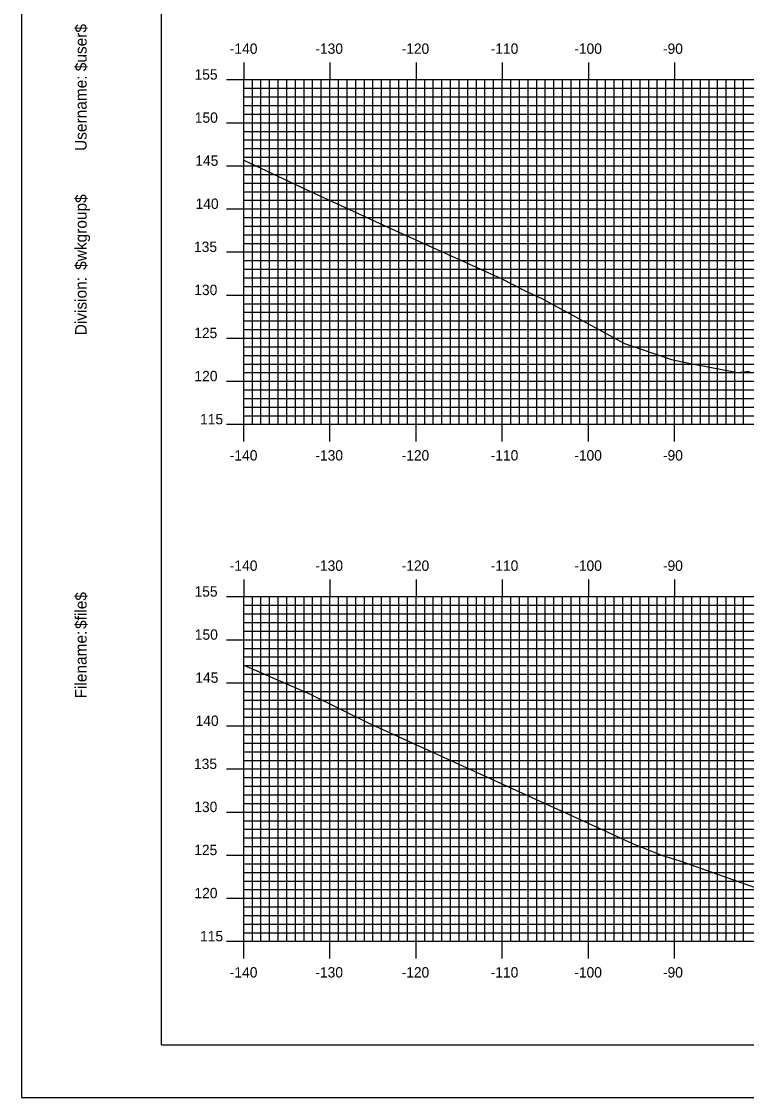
# Model space of a CAD drawing. Extents: x 852320 to 852663, y 366605 to 366825.
# Drawn here: x 852319.7 to 852403.8, y 366604.9 to 366729.8 of the extents above; entities that cross this region are included whole.
import ezdxf

# ---------------------------------------------------------------- set-up
doc = ezdxf.new("R2010")
doc.units = 0
for name, color, linetype in [('BORDER', 7, 'Continuous'), ('H_V ANNOTATION', 7, 'Continuous'), ('MAJOR', 7, 'Continuous'), ('MINOR', 7, 'Continuous'), ('PLOT BOUNDARY', 7, 'Continuous'), ('S_Roadway_Centerline', 7, 'Continuous')]:
    doc.layers.add(name, color=color, linetype=linetype)

msp = doc.modelspace()

# ---------------------------------------------------------------- linework, layer by layer
at = {"layer": 'BORDER'}
msp.add_lwpolyline([(852335.88, 366611.06), (852655.88, 366611.06), (852655.88, 366821.06), (852335.88, 366821.06)], close=True, dxfattribs=at)
at = {"layer": 'MAJOR'}
for p, q in [((852345.48, 366725.06), (852345.48, 366723.06)), ((852355.48, 366725.06), (852355.48, 366723.06)), ((852365.48, 366725.06), (852365.48, 366723.06)), ((852375.48, 366725.06), (852375.48, 366723.06)), ((852385.48, 366725.06), (852385.48, 366723.06)), ((852395.48, 366725.06), (852395.48, 366723.06)), ((852343.47, 366723.06), (852345.48, 366723.06)), ((852345.48, 366723.06), (852625.48, 366723.06)), ((852345.48, 366683.06), (852345.48, 366723.06)), ((852345.48, 366683.06), (852345.48, 366723.06)), ((852345.48, 366723.06), (852625.48, 366723.06)), ((852355.48, 366683.06), (852355.48, 366723.06)), ((852365.48, 366683.06), (852365.48, 366723.06)), ((852375.48, 366683.06), (852375.48, 366723.06)), ((852385.48, 366683.06), (852385.48, 366723.06)), ((852395.48, 366683.06), (852395.48, 366723.06)), ((852343.47, 366718.06), (852345.48, 366718.06)), ((852345.48, 366718.06), (852625.48, 366718.06)), ((852343.47, 366713.06), (852345.48, 366713.06)), ((852345.48, 366713.06), (852625.48, 366713.06)), ((852343.47, 366708.06), (852345.48, 366708.06)), ((852345.48, 366708.06), (852625.48, 366708.06)), ((852343.47, 366703.06), (852345.48, 366703.06)), ((852345.48, 366703.06), (852625.48, 366703.06)), ((852343.47, 366698.06), (852345.48, 366698.06)), ((852345.48, 366698.06), (852625.48, 366698.06)), ((852343.47, 366693.06), (852345.48, 366693.06)), ((852345.48, 366693.06), (852625.48, 366693.06)), ((852343.47, 366688.06), (852345.48, 366688.06)), ((852345.48, 366688.06), (852625.48, 366688.06)), ((852343.47, 366683.06), (852345.48, 366683.06)), ((852345.48, 366683.06), (852625.48, 366683.06)), ((852345.48, 366683.06), (852625.48, 366683.06)), ((852345.48, 366681.05), (852345.48, 366683.06)), ((852355.48, 366681.05), (852355.48, 366683.06)), ((852365.48, 366681.05), (852365.48, 366683.06)), ((852375.48, 366681.05), (852375.48, 366683.06)), ((852385.48, 366681.05), (852385.48, 366683.06)), ((852395.48, 366681.05), (852395.48, 366683.06)), ((852345.48, 366665.06), (852345.48, 366663.06)), ((852355.48, 366665.06), (852355.48, 366663.06)), ((852365.48, 366665.06), (852365.48, 366663.06)), ((852375.48, 366665.06), (852375.48, 366663.06)), ((852385.48, 366665.06), (852385.48, 366663.06)), ((852395.48, 366665.06), (852395.48, 366663.06)), ((852343.47, 366663.06), (852345.48, 366663.06)), ((852345.48, 366663.06), (852625.48, 366663.06)), ((852345.48, 366623.06), (852345.48, 366663.06)), ((852345.48, 366623.06), (852345.48, 366663.06)), ((852345.48, 366663.06), (852625.48, 366663.06)), ((852355.48, 366623.06), (852355.48, 366663.06)), ((852365.48, 366623.06), (852365.48, 366663.06)), ((852375.48, 366623.06), (852375.48, 366663.06)), ((852385.48, 366623.06), (852385.48, 366663.06)), ((852395.48, 366623.06), (852395.48, 366663.06)), ((852343.47, 366658.06), (852345.48, 366658.06)), ((852345.48, 366658.06), (852625.48, 366658.06)), ((852343.47, 366653.06), (852345.48, 366653.06)), ((852345.48, 366653.06), (852625.48, 366653.06)), ((852343.47, 366648.06), (852345.48, 366648.06)), ((852345.48, 366648.06), (852625.48, 366648.06)), ((852343.47, 366643.06), (852345.48, 366643.06)), ((852345.48, 366643.06), (852625.48, 366643.06)), ((852343.47, 366638.06), (852345.48, 366638.06)), ((852345.48, 366638.06), (852625.48, 366638.06)), ((852343.47, 366633.06), (852345.48, 366633.06)), ((852345.48, 366633.06), (852625.48, 366633.06)), ((852343.47, 366628.06), (852345.48, 366628.06)), ((852345.48, 366628.06), (852625.48, 366628.06)), ((852343.47, 366623.06), (852345.48, 366623.06)), ((852345.48, 366623.06), (852625.48, 366623.06)), ((852345.48, 366623.06), (852625.48, 366623.06)), ((852345.48, 366621.05), (852345.48, 366623.06)), ((852355.48, 366621.05), (852355.48, 366623.06)), ((852365.48, 366621.05), (852365.48, 366623.06)), ((852375.48, 366621.05), (852375.48, 366623.06)), ((852385.48, 366621.05), (852385.48, 366623.06)), ((852395.48, 366621.05), (852395.48, 366623.06))]:
    msp.add_line(p, q, dxfattribs=at)
at = {"layer": 'MINOR'}
for p, q in [((852346.48, 366683.06), (852346.48, 366723.06)), ((852347.48, 366683.06), (852347.48, 366723.06)), ((852348.48, 366683.06), (852348.48, 366723.06)), ((852349.48, 366683.06), (852349.48, 366723.06)), ((852350.48, 366683.06), (852350.48, 366723.06)), ((852351.48, 366683.06), (852351.48, 366723.06)), ((852352.48, 366683.06), (852352.48, 366723.06)), ((852353.48, 366683.06), (852353.48, 366723.06)), ((852354.48, 366683.06), (852354.48, 366723.06)), ((852356.48, 366683.06), (852356.48, 366723.06)), ((852357.48, 366683.06), (852357.48, 366723.06)), ((852358.48, 366683.06), (852358.48, 366723.06)), ((852359.48, 366683.06), (852359.48, 366723.06)), ((852360.48, 366683.06), (852360.48, 366723.06)), ((852361.48, 366683.06), (852361.48, 366723.06)), ((852362.48, 366683.06), (852362.48, 366723.06)), ((852363.48, 366683.06), (852363.48, 366723.06)), ((852364.48, 366683.06), (852364.48, 366723.06)), ((852366.48, 366683.06), (852366.48, 366723.06)), ((852367.48, 366683.06), (852367.48, 366723.06)), ((852368.48, 366683.06), (852368.48, 366723.06)), ((852369.48, 366683.06), (852369.48, 366723.06)), ((852370.48, 366683.06), (852370.48, 366723.06)), ((852371.48, 366683.06), (852371.48, 366723.06)), ((852372.48, 366683.06), (852372.48, 366723.06)), ((852373.48, 366683.06), (852373.48, 366723.06)), ((852374.48, 366683.06), (852374.48, 366723.06)), ((852376.48, 366683.06), (852376.48, 366723.06)), ((852377.48, 366683.06), (852377.48, 366723.06)), ((852378.48, 366683.06), (852378.48, 366723.06)), ((852379.48, 366683.06), (852379.48, 366723.06)), ((852380.48, 366683.06), (852380.48, 366723.06)), ((852381.48, 366683.06), (852381.48, 366723.06)), ((852382.48, 366683.06), (852382.48, 366723.06)), ((852383.48, 366683.06), (852383.48, 366723.06)), ((852384.48, 366683.06), (852384.48, 366723.06)), ((852386.48, 366683.06), (852386.48, 366723.06)), ((852387.48, 366683.06), (852387.48, 366723.06)), ((852388.48, 366683.06), (852388.48, 366723.06)), ((852389.48, 366683.06), (852389.48, 366723.06)), ((852390.48, 366683.06), (852390.48, 366723.06)), ((852391.48, 366683.06), (852391.48, 366723.06)), ((852392.48, 366683.06), (852392.48, 366723.06)), ((852393.48, 366683.06), (852393.48, 366723.06)), ((852394.48, 366683.06), (852394.48, 366723.06)), ((852396.48, 366683.06), (852396.48, 366723.06)), ((852397.48, 366683.06), (852397.48, 366723.06)), ((852398.48, 366683.06), (852398.48, 366723.06)), ((852399.48, 366683.06), (852399.48, 366723.06)), ((852400.48, 366683.06), (852400.48, 366723.06)), ((852401.48, 366683.06), (852401.48, 366723.06)), ((852402.48, 366683.06), (852402.48, 366723.06)), ((852403.48, 366683.06), (852403.48, 366723.06)), ((852345.48, 366722.06), (852625.48, 366722.06)), ((852345.48, 366722.06), (852347.48, 366722.06)), ((852345.48, 366721.06), (852625.48, 366721.06)), ((852345.48, 366721.06), (852347.48, 366721.06)), ((852345.48, 366720.06), (852625.48, 366720.06)), ((852345.48, 366720.06), (852347.48, 366720.06)), ((852345.48, 366719.06), (852625.48, 366719.06)), ((852345.48, 366719.06), (852347.48, 366719.06)), ((852345.48, 366717.06), (852625.48, 366717.06)), ((852345.48, 366717.06), (852347.48, 366717.06)), ((852345.48, 366716.06), (852625.48, 366716.06)), ((852345.48, 366716.06), (852347.48, 366716.06)), ((852345.48, 366715.06), (852625.48, 366715.06)), ((852345.48, 366715.06), (852347.48, 366715.06)), ((852345.48, 366714.06), (852625.48, 366714.06)), ((852345.48, 366714.06), (852347.48, 366714.06)), ((852345.48, 366712.06), (852625.48, 366712.06)), ((852345.48, 366712.06), (852347.48, 366712.06)), ((852345.48, 366711.06), (852625.48, 366711.06)), ((852345.48, 366711.06), (852347.48, 366711.06)), ((852345.48, 366710.06), (852625.48, 366710.06)), ((852345.48, 366710.06), (852347.48, 366710.06)), ((852345.48, 366709.06), (852625.48, 366709.06)), ((852345.48, 366709.06), (852347.48, 366709.06)), ((852345.48, 366707.06), (852625.48, 366707.06)), ((852345.48, 366707.06), (852347.48, 366707.06)), ((852345.48, 366706.06), (852625.48, 366706.06)), ((852345.48, 366706.06), (852347.48, 366706.06)), ((852345.48, 366705.06), (852625.48, 366705.06)), ((852345.48, 366705.06), (852347.48, 366705.06)), ((852345.48, 366704.06), (852625.48, 366704.06)), ((852345.48, 366704.06), (852347.48, 366704.06)), ((852345.48, 366702.06), (852625.48, 366702.06)), ((852345.48, 366702.06), (852347.48, 366702.06)), ((852345.48, 366701.06), (852625.48, 366701.06)), ((852345.48, 366701.06), (852347.48, 366701.06)), ((852345.48, 366700.06), (852625.48, 366700.06)), ((852345.48, 366700.06), (852347.48, 366700.06)), ((852345.48, 366699.06), (852625.48, 366699.06)), ((852345.48, 366699.06), (852347.48, 366699.06)), ((852345.48, 366697.06), (852625.48, 366697.06)), ((852345.48, 366697.06), (852347.48, 366697.06)), ((852345.48, 366696.06), (852625.48, 366696.06)), ((852345.48, 366696.06), (852347.48, 366696.06)), ((852345.48, 366695.06), (852625.48, 366695.06)), ((852345.48, 366695.06), (852347.48, 366695.06)), ((852345.48, 366694.06), (852625.48, 366694.06)), ((852345.48, 366694.06), (852347.48, 366694.06)), ((852345.48, 366692.06), (852625.48, 366692.06)), ((852345.48, 366692.06), (852347.48, 366692.06)), ((852345.48, 366691.06), (852625.48, 366691.06)), ((852345.48, 366691.06), (852347.48, 366691.06)), ((852345.48, 366690.06), (852625.48, 366690.06)), ((852345.48, 366690.06), (852347.48, 366690.06)), ((852345.48, 366689.06), (852625.48, 366689.06)), ((852345.48, 366689.06), (852347.48, 366689.06)), ((852345.48, 366687.06), (852625.48, 366687.06)), ((852345.48, 366687.06), (852347.48, 366687.06)), ((852345.48, 366686.06), (852625.48, 366686.06)), ((852345.48, 366686.06), (852347.48, 366686.06)), ((852345.48, 366685.06), (852625.48, 366685.06)), ((852345.48, 366685.06), (852347.48, 366685.06)), ((852345.48, 366684.06), (852625.48, 366684.06)), ((852345.48, 366684.06), (852347.48, 366684.06)), ((852346.48, 366623.06), (852346.48, 366663.06)), ((852347.48, 366623.06), (852347.48, 366663.06)), ((852348.48, 366623.06), (852348.48, 366663.06)), ((852349.48, 366623.06), (852349.48, 366663.06)), ((852350.48, 366623.06), (852350.48, 366663.06)), ((852351.48, 366623.06), (852351.48, 366663.06)), ((852352.48, 366623.06), (852352.48, 366663.06)), ((852353.48, 366623.06), (852353.48, 366663.06)), ((852354.48, 366623.06), (852354.48, 366663.06)), ((852356.48, 366623.06), (852356.48, 366663.06)), ((852357.48, 366623.06), (852357.48, 366663.06)), ((852358.48, 366623.06), (852358.48, 366663.06)), ((852359.48, 366623.06), (852359.48, 366663.06)), ((852360.48, 366623.06), (852360.48, 366663.06)), ((852361.48, 366623.06), (852361.48, 366663.06)), ((852362.48, 366623.06), (852362.48, 366663.06)), ((852363.48, 366623.06), (852363.48, 366663.06)), ((852364.48, 366623.06), (852364.48, 366663.06)), ((852366.48, 366623.06), (852366.48, 366663.06)), ((852367.48, 366623.06), (852367.48, 366663.06)), ((852368.48, 366623.06), (852368.48, 366663.06)), ((852369.48, 366623.06), (852369.48, 366663.06)), ((852370.48, 366623.06), (852370.48, 366663.06)), ((852371.48, 366623.06), (852371.48, 366663.06)), ((852372.48, 366623.06), (852372.48, 366663.06)), ((852373.48, 366623.06), (852373.48, 366663.06)), ((852374.48, 366623.06), (852374.48, 366663.06)), ((852376.48, 366623.06), (852376.48, 366663.06)), ((852377.48, 366623.06), (852377.48, 366663.06)), ((852378.48, 366623.06), (852378.48, 366663.06)), ((852379.48, 366623.06), (852379.48, 366663.06)), ((852380.48, 366623.06), (852380.48, 366663.06)), ((852381.48, 366623.06), (852381.48, 366663.06)), ((852382.48, 366623.06), (852382.48, 366663.06)), ((852383.48, 366623.06), (852383.48, 366663.06)), ((852384.48, 366623.06), (852384.48, 366663.06)), ((852386.48, 366623.06), (852386.48, 366663.06)), ((852387.48, 366623.06), (852387.48, 366663.06)), ((852388.48, 366623.06), (852388.48, 366663.06)), ((852389.48, 366623.06), (852389.48, 366663.06)), ((852390.48, 366623.06), (852390.48, 366663.06)), ((852391.48, 366623.06), (852391.48, 366663.06)), ((852392.48, 366623.06), (852392.48, 366663.06)), ((852393.48, 366623.06), (852393.48, 366663.06)), ((852394.48, 366623.06), (852394.48, 366663.06)), ((852396.48, 366623.06), (852396.48, 366663.06)), ((852397.48, 366623.06), (852397.48, 366663.06)), ((852398.48, 366623.06), (852398.48, 366663.06)), ((852399.48, 366623.06), (852399.48, 366663.06)), ((852400.48, 366623.06), (852400.48, 366663.06)), ((852401.48, 366623.06), (852401.48, 366663.06)), ((852402.48, 366623.06), (852402.48, 366663.06)), ((852403.48, 366623.06), (852403.48, 366663.06)), ((852345.48, 366662.06), (852625.48, 366662.06)), ((852345.48, 366662.06), (852347.48, 366662.06)), ((852345.48, 366661.06), (852625.48, 366661.06)), ((852345.48, 366661.06), (852347.48, 366661.06)), ((852345.48, 366660.06), (852625.48, 366660.06)), ((852345.48, 366660.06), (852347.48, 366660.06)), ((852345.48, 366659.06), (852625.48, 366659.06)), ((852345.48, 366659.06), (852347.48, 366659.06)), ((852345.48, 366657.06), (852625.48, 366657.06)), ((852345.48, 366657.06), (852347.48, 366657.06)), ((852345.48, 366656.06), (852625.48, 366656.06)), ((852345.48, 366656.06), (852347.48, 366656.06)), ((852345.48, 366655.06), (852625.48, 366655.06)), ((852345.48, 366655.06), (852347.48, 366655.06)), ((852345.48, 366654.06), (852625.48, 366654.06)), ((852345.48, 366654.06), (852347.48, 366654.06)), ((852345.48, 366652.06), (852625.48, 366652.06)), ((852345.48, 366652.06), (852347.48, 366652.06)), ((852345.48, 366651.06), (852625.48, 366651.06)), ((852345.48, 366651.06), (852347.48, 366651.06)), ((852345.48, 366650.06), (852625.48, 366650.06)), ((852345.48, 366650.06), (852347.48, 366650.06)), ((852345.48, 366649.06), (852625.48, 366649.06)), ((852345.48, 366649.06), (852347.48, 366649.06)), ((852345.48, 366647.06), (852625.48, 366647.06)), ((852345.48, 366647.06), (852347.48, 366647.06)), ((852345.48, 366646.06), (852625.48, 366646.06)), ((852345.48, 366646.06), (852347.48, 366646.06)), ((852345.48, 366645.06), (852625.48, 366645.06)), ((852345.48, 366645.06), (852347.48, 366645.06)), ((852345.48, 366644.06), (852625.48, 366644.06)), ((852345.48, 366644.06), (852347.48, 366644.06)), ((852345.48, 366642.06), (852625.48, 366642.06)), ((852345.48, 366642.06), (852347.48, 366642.06)), ((852345.48, 366641.06), (852625.48, 366641.06)), ((852345.48, 366641.06), (852347.48, 366641.06)), ((852345.48, 366640.06), (852625.48, 366640.06)), ((852345.48, 366640.06), (852347.48, 366640.06)), ((852345.48, 366639.06), (852625.48, 366639.06)), ((852345.48, 366639.06), (852347.48, 366639.06)), ((852345.48, 366637.06), (852625.48, 366637.06)), ((852345.48, 366637.06), (852347.48, 366637.06)), ((852345.48, 366636.06), (852625.48, 366636.06)), ((852345.48, 366636.06), (852347.48, 366636.06)), ((852345.48, 366635.06), (852625.48, 366635.06)), ((852345.48, 366635.06), (852347.48, 366635.06)), ((852345.48, 366634.06), (852625.48, 366634.06)), ((852345.48, 366634.06), (852347.48, 366634.06)), ((852345.48, 366632.06), (852625.48, 366632.06)), ((852345.48, 366632.06), (852347.48, 366632.06)), ((852345.48, 366631.06), (852625.48, 366631.06)), ((852345.48, 366631.06), (852347.48, 366631.06)), ((852345.48, 366630.06), (852625.48, 366630.06)), ((852345.48, 366630.06), (852347.48, 366630.06)), ((852345.48, 366629.06), (852625.48, 366629.06)), ((852345.48, 366629.06), (852347.48, 366629.06)), ((852345.48, 366627.06), (852625.48, 366627.06)), ((852345.48, 366627.06), (852347.48, 366627.06)), ((852345.48, 366626.06), (852625.48, 366626.06)), ((852345.48, 366626.06), (852347.48, 366626.06)), ((852345.48, 366625.06), (852625.48, 366625.06)), ((852345.48, 366625.06), (852347.48, 366625.06)), ((852345.48, 366624.06), (852625.48, 366624.06)), ((852345.48, 366624.06), (852347.48, 366624.06))]:
    msp.add_line(p, q, dxfattribs=at)
at = {"layer": 'PLOT BOUNDARY'}
msp.add_lwpolyline([(852319.69, 366604.94), (852659.69, 366604.94), (852659.69, 366824.94), (852319.69, 366824.94)], close=True, dxfattribs=at)
at = {"layer": 'S_Roadway_Centerline'}
for points in [[(852345.48, 366713.71), (852352.64, 366710.35), (852361.77, 366706.12), (852375.36, 366700), (852378.14, 366698.54), (852380.08, 366697.68), (852389.67, 366692.45), (852395.11, 366690.6), (852397.13, 366690.14), (852402.8, 366689.08), (852404.16, 366689.21)], [(852345.48, 366655.12), (852353.1, 366651.77), (852359.91, 366648.4), (852366.89, 366645.23), (852386.32, 366636.38), (852390.69, 366634.39), (852393.95, 366633.07), (852396.08, 366632.39), (852407.78, 366628.25)]]:
    msp.add_lwpolyline(points, dxfattribs=at)

# ---------------------------------------------------------------- texts
at = {"layer": 'BORDER'}
for s, p in [('$user$', (852327.25, 366724.04)), ('Username:', (852327.25, 366714.79)), ('$wkgroup$', (852327.25, 366700.99)), ('Division:', (852327.25, 366693.39)), ('$file$', (852327.25, 366659.31)), ('Filename:', (852327.25, 366651.25))]:
    msp.add_text(s, height=1.339, rotation=90, dxfattribs=at).set_placement(p)
at = {"layer": 'H_V ANNOTATION'}
for s, p in [('-140', (852343.86, 366726.06)), ('-130', (852353.79, 366726.06)), ('-120', (852363.8, 366726.06)), ('-110', (852374.14, 366726.06)), ('-100', (852383.84, 366726.06)), ('-90', (852394.13, 366726.06)), ('155', (852339.77, 366723.06)), ('150', (852339.8, 366718.06)), ('145', (852339.86, 366713.06)), ('140', (852339.89, 366708.06)), ('135', (852339.71, 366703.06)), ('130', (852339.74, 366698.06)), ('125', (852339.73, 366693.06)), ('120', (852339.76, 366688.06)), ('115', (852340.41, 366683.06)), ('-140', (852343.86, 366678.86)), ('-130', (852353.79, 366678.86)), ('-120', (852363.8, 366678.86)), ('-110', (852374.14, 366678.86)), ('-100', (852383.84, 366678.86)), ('-90', (852394.13, 366678.86)), ('-140', (852343.86, 366666.06)), ('-130', (852353.79, 366666.06)), ('-120', (852363.8, 366666.06)), ('-110', (852374.14, 366666.06)), ('-100', (852383.84, 366666.06)), ('-90', (852394.13, 366666.06)), ('155', (852339.77, 366663.06)), ('150', (852339.8, 366658.06)), ('145', (852339.86, 366653.06)), ('140', (852339.89, 366648.06)), ('135', (852339.71, 366643.06)), ('130', (852339.74, 366638.06)), ('125', (852339.73, 366633.06)), ('120', (852339.76, 366628.06)), ('115', (852340.41, 366623.06)), ('-140', (852343.86, 366618.86)), ('-130', (852353.79, 366618.86)), ('-120', (852363.8, 366618.86)), ('-110', (852374.14, 366618.86)), ('-100', (852383.84, 366618.86)), ('-90', (852394.13, 366618.86))]:
    msp.add_text(s, height=1.2, dxfattribs=at).set_placement(p)
at = {"layer": 'MAJOR'}
for p in [(852345.47, 366683.06), (852345.47, 366623.06)]:
    msp.add_text('-', height=0.012, dxfattribs=at).set_placement(p)

doc.saveas('drawing.dxf')
